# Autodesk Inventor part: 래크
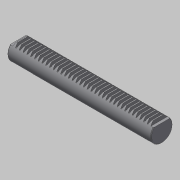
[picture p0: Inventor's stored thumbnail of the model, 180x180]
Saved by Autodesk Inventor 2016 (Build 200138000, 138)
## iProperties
Created: 2019-06
Part Number: 래크
Material: 스테인리스강
Document SubType Name: Modeling
Designer: mduedu
Density: 8.08 g/cm^3
Appearance: 기본값
Mass: 1739.85 g
Surface Area: 334.124 cm^2
Volume: 215.328 cm^3
Author: mduedu
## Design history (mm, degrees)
sketch "스케치1"
  geometry: L1 (0, 0)-(240, 0); L2 (240, 0)-(240, 34); L3 (240, 34)-(0, 34); L4 (0, 34)-(0, 0)
  constraints: 8 end point, 2 parallel, 1 horizontal, 1 perpendicular
  dimensions: "d0" = 240 distance of L1.start L1.end; "d1" = 34 distance of L1.end L2.end
extrude "돌출1" new body sketch "스케치1" stored distance "d2" = 36; taper "d3" = 0 deg
sketch "스케치2"
  geometry: L1 (0, 0)-(240, 0) reference; L2 (240, 0)-(240, 34) reference; L3 (240, 34)-(0, 34) reference; L4 (0, 34)-(0, 0) reference; L5 (9.44, 29.5)-(10.76, 29.5); L6 (12.398, 34)-(7.802, 34); L7 (10.1, 34)-(10.1, 29.5); L8 (7.802, 34)-(9.44, 29.5); L9 (12.398, 34)-(10.76, 29.5); L10 (8.53, 32)-(11.67, 32); 1 further point
  constraints: 12 end point, 2 midpoint, 2 point on line, 1 collinear, 1 horizontal, 1 parallel, 1 perpendicular, 1 symmetric about line
  dimensions: "d4" = 20 deg angle of L9 L7; "d5" = 2 distance between parallel lines of L10 L6; "d7" = 4.5 distance between parallel lines of L5 L6 (= 2.25 x d5); "d8" = 3.14 distance of L10.start L10.end; "d9" = 10.1 distance between parallel lines of L4 L7
extrude "돌출2" cut sketch "스케치2" stored distance "d10" = 36; taper "d11" = 0 deg
sketch "스케치3"
  geometry: L1 (235.52, 29.5)-(233.882, 34) reference; L2 (233.882, 34)-(232.198, 34) reference; L3 (232.198, 34)-(230.56, 29.5) reference; L4 (230.56, 29.5)-(229.24, 29.5) reference; L5 (229.24, 29.5)-(227.602, 34) reference; L6 (227.602, 34)-(225.918, 34) reference; L7 (225.918, 34)-(224.28, 29.5) reference; L8 (224.28, 29.5)-(222.96, 29.5) reference; L9 (222.96, 29.5)-(221.322, 34) reference; L10 (221.322, 34)-(219.638, 34) reference; L11 (219.638, 34)-(218, 29.5) reference; L12 (218, 29.5)-(216.68, 29.5) reference; L13 (216.68, 29.5)-(215.042, 34) reference; L14 (215.042, 34)-(213.358, 34) reference; L15 (213.358, 34)-(211.72, 29.5) reference; L16 (211.72, 29.5)-(210.4, 29.5) reference; L17 (210.4, 29.5)-(208.762, 34) reference; L18 (208.762, 34)-(207.078, 34) reference; L19 (207.078, 34)-(205.44, 29.5) reference; L20 (205.44, 29.5)-(204.12, 29.5) reference; L21 (204.12, 29.5)-(202.482, 34) reference; L22 (202.482, 34)-(200.798, 34) reference; L23 (200.798, 34)-(199.16, 29.5) reference; L24 (199.16, 29.5)-(197.84, 29.5) reference; L25 (197.84, 29.5)-(196.202, 34) reference; L26 (196.202, 34)-(194.518, 34) reference; L27 (194.518, 34)-(192.88, 29.5) reference; L28 (192.88, 29.5)-(191.56, 29.5) reference; L29 (191.56, 29.5)-(189.922, 34) reference; L30 (189.922, 34)-(188.238, 34) reference; L31 (188.238, 34)-(186.6, 29.5) reference; L32 (186.6, 29.5)-(185.28, 29.5) reference; L33 (185.28, 29.5)-(183.642, 34) reference; L34 (183.642, 34)-(181.958, 34) reference; L35 (181.958, 34)-(180.32, 29.5) reference; L36 (180.32, 29.5)-(179, 29.5) reference; L37 (179, 29.5)-(177.362, 34) reference; L38 (177.362, 34)-(175.678, 34) reference; L39 (175.678, 34)-(174.04, 29.5) reference; L40 (174.04, 29.5)-(172.72, 29.5) reference; L41 (172.72, 29.5)-(171.082, 34) reference; L42 (171.082, 34)-(169.398, 34) reference; L43 (169.398, 34)-(167.76, 29.5) reference; L44 (167.76, 29.5)-(166.44, 29.5) reference; L45 (166.44, 29.5)-(164.802, 34) reference; L46 (164.802, 34)-(163.118, 34) reference; L47 (163.118, 34)-(161.48, 29.5) reference; L48 (161.48, 29.5)-(160.16, 29.5) reference; L49 (160.16, 29.5)-(158.522, 34) reference; L50 (158.522, 34)-(156.838, 34) reference; L51 (156.838, 34)-(155.2, 29.5) reference; L52 (155.2, 29.5)-(153.88, 29.5) reference; L53 (153.88, 29.5)-(152.242, 34) reference; L54 (152.242, 34)-(150.558, 34) reference; L55 (150.558, 34)-(148.92, 29.5) reference; L56 (148.92, 29.5)-(147.6, 29.5) reference; L57 (147.6, 29.5)-(145.962, 34) reference; L58 (145.962, 34)-(144.278, 34) reference; L59 (144.278, 34)-(142.64, 29.5) reference; L60 (142.64, 29.5)-(141.32, 29.5) reference; L61 (141.32, 29.5)-(139.682, 34) reference; L62 (139.682, 34)-(137.998, 34) reference; L63 (137.998, 34)-(136.36, 29.5) reference; L64 (136.36, 29.5)-(135.04, 29.5) reference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; 1 further point
  constraints: 16 end point, 4 parallel, 2 horizontal, 2 perpendicular
extrude "돌출3" cut sketch "스케치3" stored distance "d18" = 36; taper "d19" = 0 deg
sketch "스케치4"
  geometry: L1 (4.48, 29.5)-(0, 29.5) reference; L2 (0, 29.5)-(0, 0) reference; L3 (0, 0)-(240, 0) reference; L4 (240, 0)-(240, 29.5) reference; L5 (240, 29.5)-(235.52, 29.5) reference; L6 (235.52, 29.5)-(233.882, 34) reference; L7 (233.882, 34)-(232.198, 34) reference; L8 (232.198, 34)-(230.56, 29.5) reference; L9 (230.56, 29.5)-(229.24, 29.5) reference; L10 (229.24, 29.5)-(227.602, 34) reference; L11 (227.602, 34)-(225.918, 34) reference; L12 (225.918, 34)-(224.28, 29.5) reference; L13 (224.28, 29.5)-(222.96, 29.5) reference; L14 (222.96, 29.5)-(221.322, 34) reference; L15 (221.322, 34)-(219.638, 34) reference; L16 (219.638, 34)-(218, 29.5) reference; L17 (218, 29.5)-(216.68, 29.5) reference; L18 (216.68, 29.5)-(215.042, 34) reference; L19 (215.042, 34)-(213.358, 34) reference; L20 (213.358, 34)-(211.72, 29.5) reference; L21 (211.72, 29.5)-(210.4, 29.5) reference; L22 (210.4, 29.5)-(208.762, 34) reference; L23 (208.762, 34)-(207.078, 34) reference; L24 (207.078, 34)-(205.44, 29.5) reference; L25 (205.44, 29.5)-(204.12, 29.5) reference; L26 (204.12, 29.5)-(202.482, 34) reference; L27 (202.482, 34)-(200.798, 34) reference; L28 (200.798, 34)-(199.16, 29.5) reference; L29 (199.16, 29.5)-(197.84, 29.5) reference; L30 (197.84, 29.5)-(196.202, 34) reference; L31 (196.202, 34)-(194.518, 34) reference; L32 (194.518, 34)-(192.88, 29.5) reference; L33 (192.88, 29.5)-(191.56, 29.5) reference; L34 (191.56, 29.5)-(189.922, 34) reference; L35 (189.922, 34)-(188.238, 34) reference; L36 (188.238, 34)-(186.6, 29.5) reference; L37 (186.6, 29.5)-(185.28, 29.5) reference; L38 (185.28, 29.5)-(183.642, 34) reference; L39 (183.642, 34)-(181.958, 34) reference; L40 (181.958, 34)-(180.32, 29.5) reference; L41 (180.32, 29.5)-(179, 29.5) reference; L42 (179, 29.5)-(177.362, 34) reference; L43 (177.362, 34)-(175.678, 34) reference; L44 (175.678, 34)-(174.04, 29.5) reference; L45 (174.04, 29.5)-(172.72, 29.5) reference; L46 (172.72, 29.5)-(171.082, 34) reference; L47 (171.082, 34)-(169.398, 34) reference; L48 (169.398, 34)-(167.76, 29.5) reference; L49 (167.76, 29.5)-(166.44, 29.5) reference; L50 (166.44, 29.5)-(164.802, 34) reference; L51 (164.802, 34)-(163.118, 34) reference; L52 (163.118, 34)-(161.48, 29.5) reference; L53 (161.48, 29.5)-(160.16, 29.5) reference; L54 (160.16, 29.5)-(158.522, 34) reference; L55 (158.522, 34)-(156.838, 34) reference; L56 (156.838, 34)-(155.2, 29.5) reference; L57 (155.2, 29.5)-(153.88, 29.5) reference; L58 (153.88, 29.5)-(152.242, 34) reference; L59 (152.242, 34)-(150.558, 34) reference; L60 (150.558, 34)-(148.92, 29.5) reference; L61 (148.92, 29.5)-(147.6, 29.5) reference; L62 (147.6, 29.5)-(145.962, 34) reference; L63 (145.962, 34)-(144.278, 34) reference; L64 (144.278, 34)-(142.64, 29.5) reference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; 1 further point
  constraints: 8 end point, 2 parallel, 1 horizontal, 1 perpendicular, 1 point on line
  dimensions: "d20" = 36 distance between parallel lines of L156 L2; "d21" = 10 distance between parallel lines of L4 L154; "d22" = 194 distance between parallel lines of L154 L156 (derived); "d23" = 4 distance between parallel lines of L3 L155
extrude "돌출4" cut sketch "스케치4" stored distance "d24" = 36; taper "d25" = 0 deg
sketch "스케치5"
  geometry: L1 (36, 0)-(0, 0) reference; C1 r 18 at (18, 18); 2 further points
  constraints: 1 centre point, 1 midpoint, 1 tangent, 1 vertical alignment
  dimensions: "d26" = 36 diameter of C1
extrude "돌출5" sketch "스케치5" stored distance "d27" = 36; taper "d28" = 0 deg
chamfer "모따기1" distance "d29" = 1; stored, may be unused: second distance "d30" = 2, angle "d31" = 45 deg
node "솔리드1"
pattern_linear "직사각형 패턴1" dims "d14" = 6.28, "d17" = 6.28
node "투영된 루프1"
node "투영된 루프2"
node "투영된 루프3"
